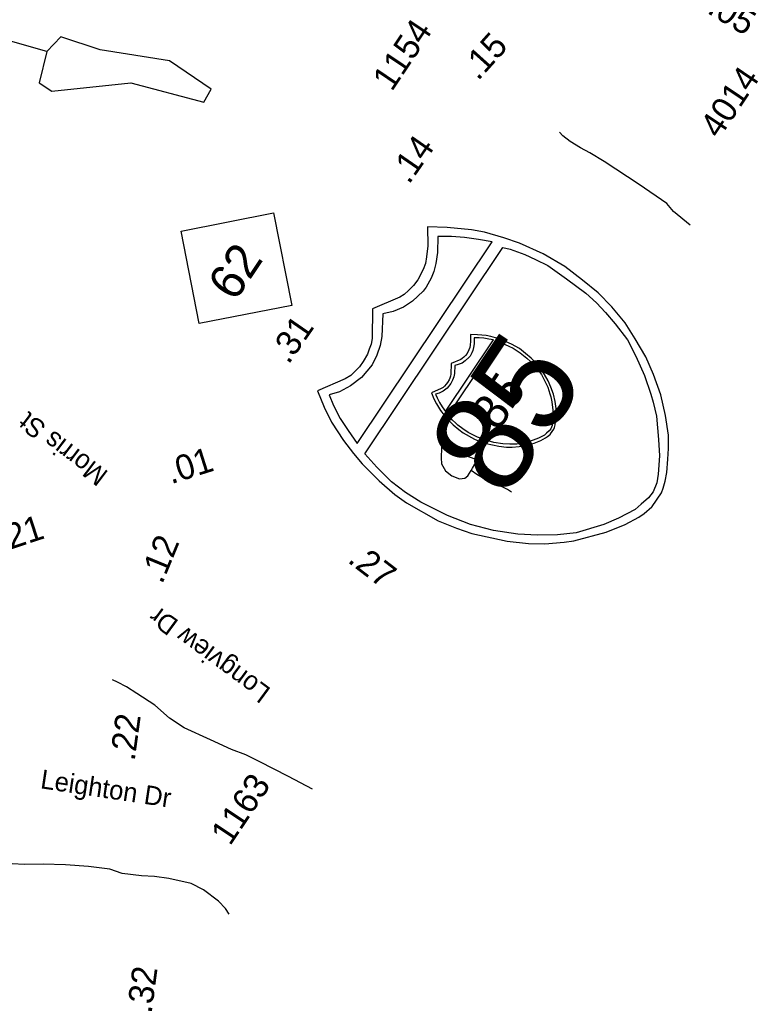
# Model space of a CAD drawing. Extents: x 1716282 to 1717158, y 799307 to 801078.
# Drawn here: x 1717073.3 to 1717126.8, y 800778.2 to 800850 of the extents above; entities that cross this region are included whole.
import ezdxf

# ---------------------------------------------------------------- set-up
doc = ezdxf.new("R2010")
doc.units = 0
for name, color, linetype in [('Exist Hydrographic Misc Water Feature', 7, 'Continuous'), ('Exist Hydrographic Pond Under 1500 Sq Ft', 7, 'Continuous'), ('Exist Road Non-System Type 51 Label', 7, 'Continuous'), ('Exist Road Primary Interstate Shield CELL', 7, 'Continuous'), ('Exist Road Primary Interstate Shield Number Label', 7, 'Continuous'), ('Exist Road Primary NC Mileage Hundredths English Label', 7, 'Continuous'), ('Exist Road Primary NC Service Mileage Hundredths English Label', 7, 'Continuous'), ('Exist Road Primary NC Shield CELL', 7, 'Continuous'), ('Exist Road Primary NC Shield Number Label', 7, 'Continuous'), ('Exist Road Secondary Mileage Hundredths English Label', 7, 'Continuous'), ('Exist Road Secondary Type 51 Number Label', 7, 'Continuous')]:
    doc.layers.add(name, color=color, linetype=linetype)

msp = doc.modelspace()

# ---------------------------------------------------------------- linework, layer by layer
at = {"layer": 'Exist Hydrographic Misc Water Feature'}
for points in [[(1717075.275, 800847.714), (1717069.753, 800849.281), (1717058.737, 800849.638), (1717052.045, 800848.203)], [(1717121.908, 800835.121), (1717120.713, 800836.121), (1717120.229, 800836.699), (1717118.216, 800838.071), (1717115.668, 800839.741), (1717114.652, 800840.363), (1717113.958, 800840.735), (1717113.223, 800841.202), (1717112.688, 800841.6), (1717112.449, 800841.87)], [(1717106.026, 800817.347), (1717106.141, 800817.516), (1717106.379, 800817.915), (1717106.397, 800818.147), (1717105.908, 800818.305), (1717105.306, 800818.504), (1717104.796, 800818.785), (1717104.412, 800819.046), (1717104.125, 800819.242), (1717103.972, 800819.276), (1717103.882, 800818.989), (1717103.872, 800818.256), (1717103.891, 800817.821), (1717104.175, 800817.312), (1717104.637, 800816.96), (1717105.198, 800816.752), (1717105.57, 800816.783), (1717105.788, 800816.948), (1717106.026, 800817.347)], [(1717106.026, 800817.347), (1717106.141, 800817.516), (1717106.379, 800817.915), (1717106.397, 800818.147), (1717105.908, 800818.305), (1717105.306, 800818.504), (1717104.796, 800818.785), (1717104.412, 800819.046), (1717104.125, 800819.242), (1717103.972, 800819.276), (1717103.882, 800818.989), (1717103.872, 800818.256), (1717103.891, 800817.821), (1717104.175, 800817.312), (1717104.637, 800816.96), (1717105.198, 800816.752), (1717105.57, 800816.783), (1717105.788, 800816.948), (1717106.026, 800817.347)], [(1717108.966, 800815.784), (1717108.666, 800815.966), (1717107.818, 800816.369), (1717106.856, 800816.812), (1717106.458, 800817.054), (1717106.026, 800817.347)], [(1717094.543, 800794.235), (1717092.798, 800795.154), (1717090.671, 800796.256), (1717089.702, 800796.741), (1717088.668, 800797.131), (1717087.14, 800797.825), (1717085.243, 800798.698), (1717084.173, 800799.394), (1717083.097, 800800.339), (1717081.811, 800801.182), (1717081.052, 800801.665), (1717080.405, 800802.003), (1717080.036, 800802.184)], [(1717088.487, 800785.187), (1717088.234, 800785.59), (1717087.716, 800786.119), (1717086.639, 800786.96), (1717085.743, 800787.397), (1717084.13, 800787.761), (1717083.078, 800787.918), (1717082.129, 800787.968), (1717080.739, 800788.145), (1717079.849, 800788.437), (1717078.306, 800788.646), (1717076.634, 800788.771), (1717075.018, 800788.821), (1717073.667, 800788.796), (1717070.947, 800788.93), (1717069.775, 800788.961), (1717069.129, 800788.943), (1717068.182, 800788.995), (1717067.691, 800789.048), (1717066.96, 800789.16), (1717066.269, 800789.281)]]:
    msp.add_lwpolyline(points, dxfattribs=at)
at = {"layer": 'Exist Hydrographic Pond Under 1500 Sq Ft'}
msp.add_lwpolyline([(1717075.275, 800847.714), (1717074.731, 800845.441), (1717075.641, 800844.832), (1717081.36, 800845.455), (1717086.646, 800844.046), (1717087.188, 800844.989), (1717084.16, 800847.052), (1717079.141, 800847.845), (1717076.302, 800848.769), (1717075.275, 800847.714)], dxfattribs=at)
at = {"layer": 'Exist Road Primary Interstate Shield CELL'}
for p, q in [((1717111.785, 800819.996), (1717112.022, 800820.351)), ((1717119.162, 800814.739), (1717119.83, 800815.738))]:
    msp.add_line(p, q, dxfattribs=at)
for points in [[(1717119.83, 800815.738), (1717119.965, 800816.058), (1717120.108, 800816.57), (1717120.216, 800817.189), (1717120.298, 800818.157), (1717120.345, 800818.948), (1717120.344, 800819.898), (1717120.133, 800821.321), (1717119.794, 800822.825), (1717119.263, 800824.309), (1717118.694, 800825.586), (1717117.935, 800826.882), (1717117.192, 800828.039), (1717116.237, 800829.202), (1717115.237, 800830.217), (1717114.109, 800831.148), (1717112.821, 800832.126), (1717111.25, 800833.046), (1717109.53, 800833.817), (1717108.405, 800834.214), (1717107.004, 800834.61), (1717106.066, 800834.796), (1717104.291, 800834.962), (1717102.862, 800834.998), (1717102.894, 800833.641), (1717102.811, 800832.825), (1717102.73, 800832.346), (1717102.551, 800831.919), (1717102.17, 800831.168), (1717101.859, 800830.744), (1717101.496, 800830.401), (1717101.192, 800830.108), (1717100.867, 800829.92), (1717098.894, 800829.07), (1717098.859, 800826.921), (1717098.793, 800826.509), (1717098.645, 800826.142), (1717098.524, 800825.774), (1717098.205, 800825.244), (1717097.931, 800824.861), (1717097.59, 800824.507), (1717097.31, 800824.233), (1717096.899, 800823.992), (1717094.906, 800823.112), (1717095.376, 800821.928), (1717095.909, 800820.861), (1717096.778, 800819.526), (1717097.505, 800818.572), (1717098.126, 800817.822), (1717099.358, 800816.587), (1717100.499, 800815.612), (1717101.358, 800815), (1717103.652, 800813.697), (1717104.976, 800813.157), (1717106.082, 800812.771), (1717108.658, 800812.219), (1717110.204, 800812.064), (1717111.373, 800812.038), (1717112.782, 800812.153), (1717113.488, 800812.255), (1717115.831, 800812.885), (1717117.203, 800813.436), (1717118.182, 800813.953), (1717118.582, 800814.237), (1717119.147, 800814.721), (1717119.162, 800814.739)], [(1717112.022, 800820.351), (1717112.07, 800820.464), (1717112.121, 800820.646), (1717112.16, 800820.867), (1717112.189, 800821.211), (1717112.205, 800821.492), (1717112.205, 800821.83), (1717112.13, 800822.336), (1717112.009, 800822.871), (1717111.821, 800823.398), (1717111.619, 800823.852), (1717111.349, 800824.313), (1717111.084, 800824.724), (1717110.745, 800825.138), (1717110.389, 800825.499), (1717109.988, 800825.83), (1717109.53, 800826.178), (1717108.972, 800826.505), (1717108.36, 800826.779), (1717107.96, 800826.92), (1717107.462, 800827.061), (1717107.128, 800827.127), (1717106.497, 800827.186), (1717105.989, 800827.199), (1717106.001, 800826.716), (1717105.971, 800826.426), (1717105.943, 800826.256), (1717105.879, 800826.104), (1717105.743, 800825.837), (1717105.633, 800825.686), (1717105.503, 800825.564), (1717105.395, 800825.46), (1717105.28, 800825.393), (1717104.579, 800825.091), (1717104.566, 800824.327), (1717104.543, 800824.181), (1717104.49, 800824.05), (1717104.447, 800823.919), (1717104.334, 800823.731), (1717104.236, 800823.594), (1717104.115, 800823.469), (1717104.015, 800823.371), (1717103.869, 800823.286), (1717103.161, 800822.973), (1717103.328, 800822.552), (1717103.517, 800822.172), (1717103.826, 800821.698), (1717104.085, 800821.358), (1717104.305, 800821.092), (1717104.743, 800820.653), (1717105.149, 800820.306), (1717105.455, 800820.088), (1717106.27, 800819.625), (1717106.741, 800819.433), (1717107.134, 800819.296), (1717108.05, 800819.099), (1717108.6, 800819.044), (1717109.015, 800819.035), (1717109.517, 800819.076), (1717109.767, 800819.113), (1717110.601, 800819.336), (1717111.088, 800819.532), (1717111.436, 800819.716), (1717111.579, 800819.817), (1717111.779, 800819.989), (1717111.785, 800819.996)]]:
    msp.add_lwpolyline(points, dxfattribs=at)
for points in [[(1717095.732, 800822.823), (1717096.056, 800822.067), (1717096.542, 800821.12), (1717097.115, 800820.239), (1717097.766, 800819.294), (1717107.56, 800833.917), (1717106.573, 800834.085), (1717105.565, 800834.231), (1717104.613, 800834.316), (1717103.627, 800834.303), (1717103.595, 800833.137), (1717103.478, 800832.351), (1717103.322, 800831.759), (1717103.141, 800831.292), (1717102.769, 800830.628), (1717102.564, 800830.357), (1717101.777, 800829.612), (1717101.136, 800829.18), (1717100.379, 800828.866), (1717099.641, 800828.697), (1717099.566, 800827.069), (1717099.449, 800826.404), (1717099.204, 800825.711), (1717098.852, 800825.01), (1717098.077, 800824.085), (1717097.284, 800823.483), (1717096.482, 800823.044)], [(1717108.34, 800833.52), (1717108.858, 800833.4), (1717109.919, 800833.002), (1717110.701, 800832.643), (1717111.592, 800832.215), (1717112.959, 800831.241), (1717114.357, 800830.208), (1717115.123, 800829.503), (1717115.781, 800828.806), (1717116.482, 800827.986), (1717117.366, 800826.827), (1717117.976, 800825.638), (1717118.604, 800824.242), (1717119.061, 800822.883), (1717119.242, 800822.304), (1717119.473, 800821.28), (1717119.619, 800819.602), (1717119.681, 800818.406), (1717119.606, 800817.074), (1717119.497, 800816.444), (1717119.237, 800815.8), (1717118.893, 800815.358), (1717118.367, 800814.894), (1717117.937, 800814.522), (1717116.73, 800813.886), (1717115.649, 800813.438), (1717113.641, 800812.831), (1717112.304, 800812.674), (1717110.853, 800812.66), (1717109.427, 800812.738), (1717107.651, 800812.991), (1717105.993, 800813.44), (1717104.311, 800814.086), (1717102.377, 800815.056), (1717101.274, 800815.758), (1717100.273, 800816.524), (1717099.792, 800816.99), (1717099.2, 800817.578), (1717098.329, 800818.547)], [(1717103.454, 800822.87), (1717103.569, 800822.601), (1717103.742, 800822.264), (1717103.946, 800821.951), (1717104.177, 800821.615), (1717107.66, 800826.814), (1717107.309, 800826.874), (1717106.95, 800826.926), (1717106.612, 800826.956), (1717106.261, 800826.952), (1717106.25, 800826.537), (1717106.208, 800826.258), (1717106.153, 800826.047), (1717106.089, 800825.881), (1717105.956, 800825.645), (1717105.883, 800825.549), (1717105.603, 800825.284), (1717105.375, 800825.13), (1717105.106, 800825.019), (1717104.844, 800824.958), (1717104.818, 800824.379), (1717104.776, 800824.143), (1717104.689, 800823.897), (1717104.564, 800823.647), (1717104.288, 800823.318), (1717104.006, 800823.105), (1717103.721, 800822.949)], [(1717107.937, 800826.673), (1717108.121, 800826.631), (1717108.499, 800826.489), (1717108.776, 800826.361), (1717109.093, 800826.209), (1717109.579, 800825.863), (1717110.076, 800825.496), (1717110.349, 800825.245), (1717110.583, 800824.997), (1717110.832, 800824.706), (1717111.146, 800824.294), (1717111.363, 800823.871), (1717111.587, 800823.375), (1717111.749, 800822.891), (1717111.813, 800822.685), (1717111.895, 800822.321), (1717111.947, 800821.725), (1717111.969, 800821.299), (1717111.943, 800820.826), (1717111.904, 800820.602), (1717111.812, 800820.373), (1717111.689, 800820.216), (1717111.502, 800820.051), (1717111.349, 800819.918), (1717110.92, 800819.692), (1717110.536, 800819.533), (1717109.822, 800819.317), (1717109.346, 800819.261), (1717108.83, 800819.256), (1717108.324, 800819.284), (1717107.692, 800819.374), (1717107.103, 800819.534), (1717106.504, 800819.763), (1717105.817, 800820.108), (1717105.425, 800820.358), (1717105.069, 800820.63), (1717104.898, 800820.796), (1717104.687, 800821.005), (1717104.378, 800821.35)]]:
    msp.add_lwpolyline(points, close=True, dxfattribs=at)
at = {"layer": 'Exist Road Primary NC Shield CELL'}
msp.add_lwpolyline([(1717086.33, 800827.99), (1717085.003, 800834.688), (1717091.701, 800836.015), (1717093.028, 800829.317)], close=True, dxfattribs=at)

# ---------------------------------------------------------------- texts
at = {"layer": 'Exist Road Non-System Type 51 Label'}
for s, rotation, p in [('Morris St', 142.8194, (1717079.806, 800817.221)), ('Longview Dr', 143.68197, (1717091.594, 800801.498)), ('Leighton Dr', 351.46091, (1717074.757, 800794.32))]:
    msp.add_text(s, height=1.3775, rotation=rotation, dxfattribs=at).set_placement(p)
at = {"layer": 'Exist Road Primary Interstate Shield Number Label'}
for height, p in [(7.1367, (1717108.524, 800815.123)), (2.5375, (1717108.002, 800820.132))]:
    msp.add_text('85', height=height, rotation=56.20506, dxfattribs=at).set_placement(p)
at = {"layer": 'Exist Road Primary NC Mileage Hundredths English Label'}
for s, rotation, p in [('.14', 55.26195, (1717101.528, 800838.029)), ('.31', 55.26195, (1717092.794, 800824.979)), ('.01', 17.54525, (1717084.284, 800816.345)), ('.21', 18.23683, (1717072.008, 800811.403))]:
    msp.add_text(s, height=1.8125, rotation=rotation, dxfattribs=at).set_placement(p)
at = {"layer": 'Exist Road Primary NC Service Mileage Hundredths English Label'}
for s, rotation, p in [('.15', 48.07024, (1717106.534, 800845.542)), ('.12', 67.59525, (1717083.634, 800809.051)), ('.22', 82.27334, (1717081.639, 800796.243)), ('.32', 82.4242, (1717082.864, 800777.935))]:
    msp.add_text(s, height=1.8125, rotation=rotation, dxfattribs=at).set_placement(p)
at = {"layer": 'Exist Road Primary NC Shield Number Label'}
msp.add_text('62', height=2.5375, rotation=56.20506, dxfattribs=at).set_placement((1717088.92, 800829.521))
at = {"layer": 'Exist Road Secondary Mileage Hundredths English Label'}
for s, rotation, p in [('.05', 328.88105, (1717123.056, 800850.555)), ('.27', 322.54923, (1717097.005, 800810.746))]:
    msp.add_text(s, height=1.8125, rotation=rotation, dxfattribs=at).set_placement(p)
at = {"layer": 'Exist Road Secondary Type 51 Number Label'}
for s, p in [('1154', (1717100.284, 800844.762)), ('4014', (1717124.015, 800841.329)), ('1163', (1717088.559, 800790.083))]:
    msp.add_text(s, height=1.8125, rotation=56.20506, dxfattribs=at).set_placement(p)

doc.saveas('drawing.dxf')
